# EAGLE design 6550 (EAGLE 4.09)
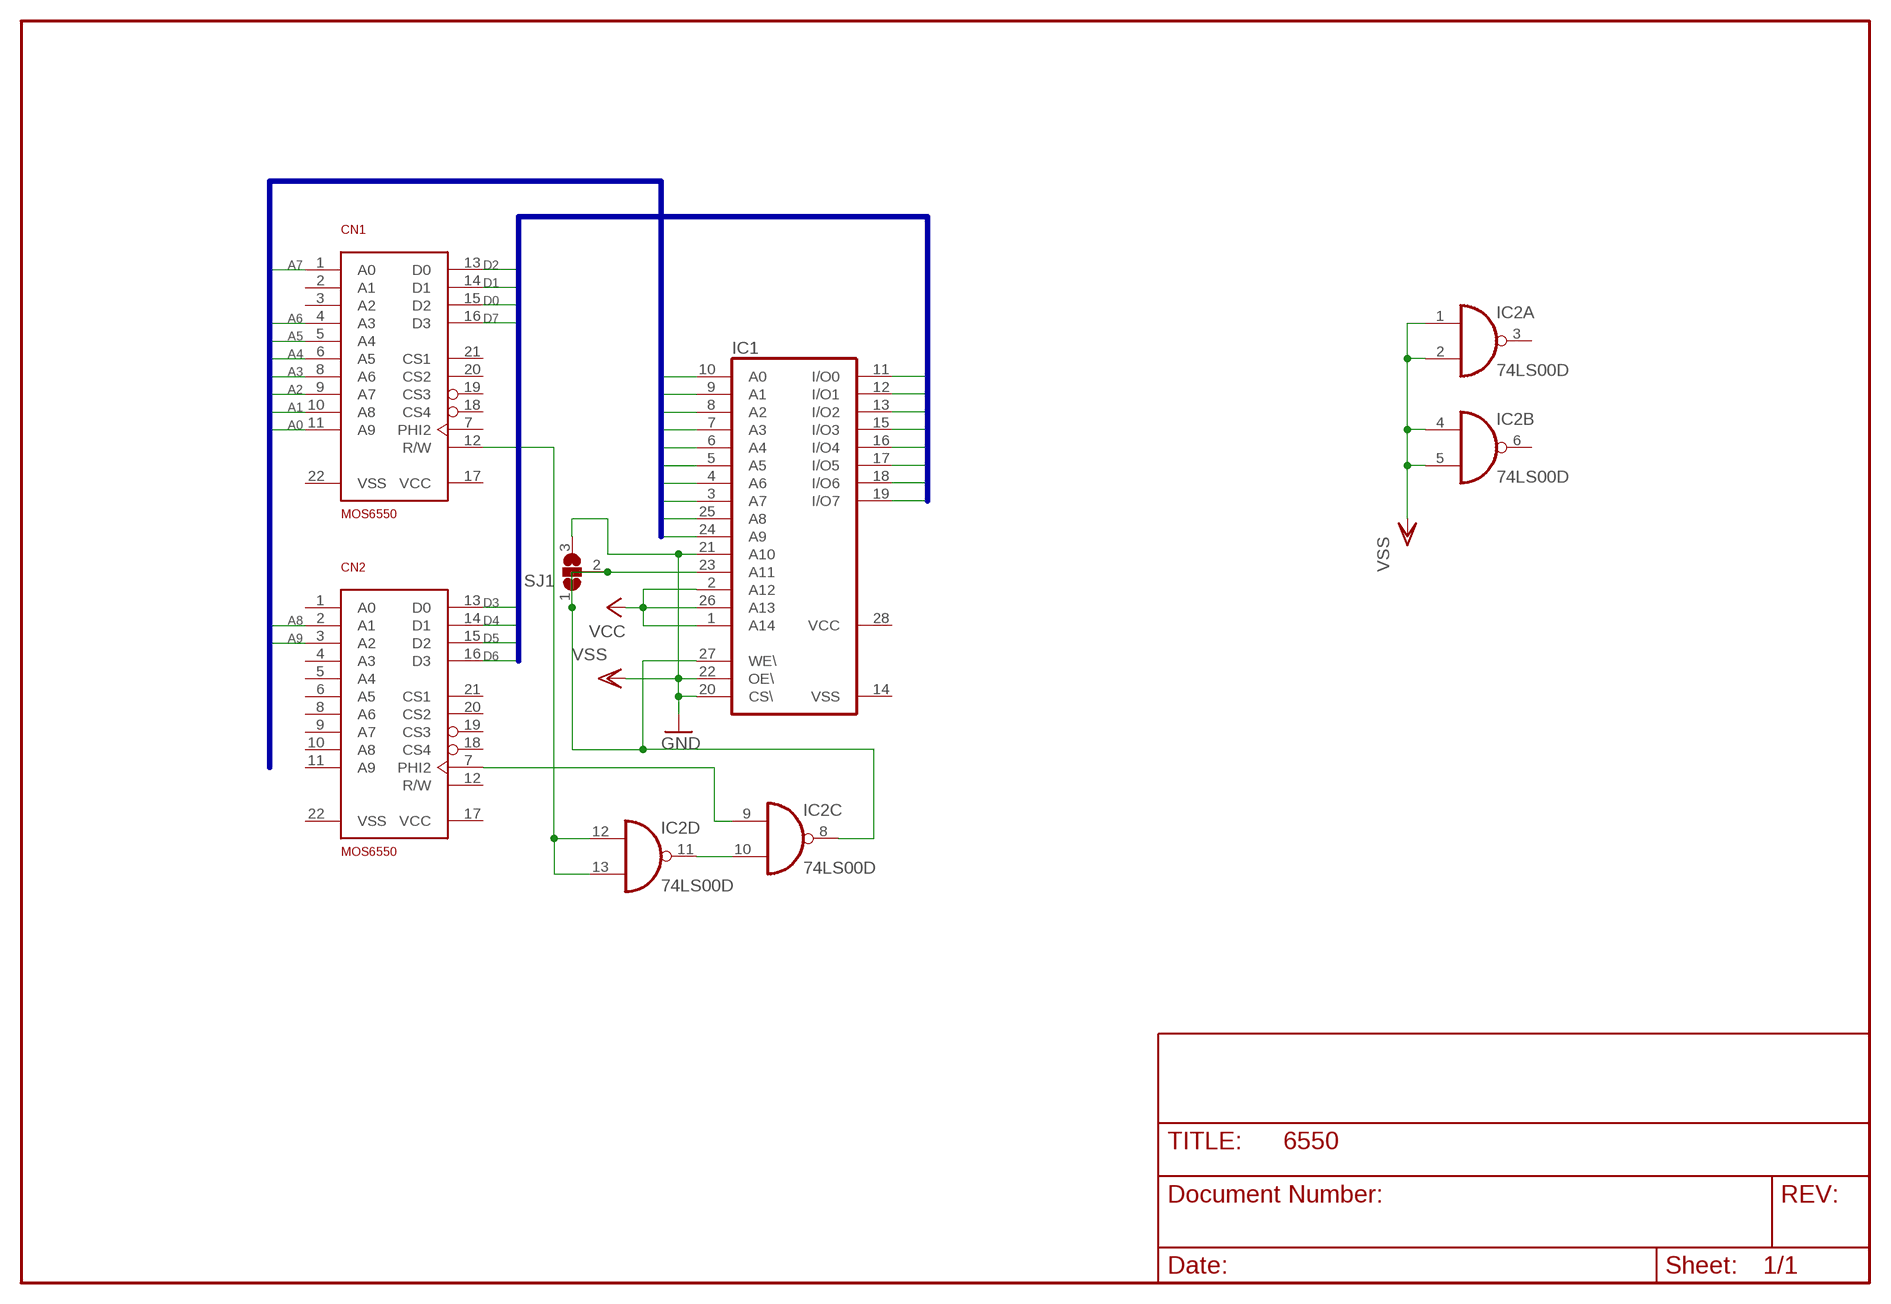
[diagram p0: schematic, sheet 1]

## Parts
CN1  MOS6550  [DIP-22]
CN2  MOS6550  [DIP-22]
IC1  62256P  [DIL28-6]
IC2  74LS00D  [SO14]
SJ1  SJ2W  [SJ_2]

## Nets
A0: CN1.11(A9) IC1.10(A0)
A1: CN1.10(A8) IC1.9(A1)
A2: CN1.9(A7) IC1.8(A2)
A3: CN1.8(A6) IC1.7(A3)
A4: CN1.6(A5) IC1.6(A4)
A5: CN1.5(A4) IC1.5(A5)
A6: CN1.4(A3) IC1.4(A6)
A7: CN1.1(A0) IC1.3(A7)
A8: CN2.2(A1) IC1.25(A8)
A9: CN2.3(A2) IC1.24(A9)
D0: CN1.15(D2) IC1.11(I/O0)
D1: CN1.14(D1) IC1.12(I/O1)
D2: CN1.13(D0) IC1.13(I/O2)
D3: CN2.13(D0) IC1.15(I/O3)
D4: CN2.14(D1) IC1.16(I/O4)
D5: CN2.15(D2) IC1.17(I/O5)
D6: CN2.16(D3) IC1.18(I/O6)
D7: CN1.16(D3) IC1.19(I/O7)
N$1: CN1.12(R/W) IC2.12(D:I0) IC2.13(D:I1)
N$2: IC2.10(C:I1) IC2.11(D:O)
N$3: CN2.7(PHI2) IC2.9(C:I0)
N$4: IC1.23(A11) IC1.27(WE\) IC2.8(C:O) SJ1.1 SJ1.2
VCC: IC1.1(A14) IC1.2(A12) IC1.26(A13)
VSS: IC1.20(CS\) IC1.21(A10) IC1.22(OE\) IC2.1(A:I0) IC2.2(A:I1) IC2.4(B:I0) IC2.5(B:I1) SJ1.3 ; supply symbol labelled GND
Unconnected: CN1.2(A1) CN1.3(A2) CN1.7(PHI2) CN1.18(CS4) CN1.19(CS3) CN1.20(CS2) CN1.21(CS1) CN2.1(A0) CN2.4(A3) CN2.5(A4) CN2.6(A5) CN2.8(A6) CN2.9(A7) CN2.10(A8) CN2.11(A9) CN2.12(R/W) CN2.18(CS4) CN2.19(CS3) CN2.20(CS2) CN2.21(CS1) IC2.3(A:O) IC2.6(B:O)

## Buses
A[0..9]
D[0..7]

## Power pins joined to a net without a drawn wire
VCC: CN1.17(VCC) CN2.17(VCC) IC1.28(VCC) IC2.14(P:VCC)
VSS: CN1.22(VSS) CN2.22(VSS) IC1.14(VSS) IC2.7(P:GND)

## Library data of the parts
CN1 CN2 = 65XXX:MOS6550
IC1 = memory-hitachi:62256P: MEMORY
IC2 = 74xx-eu:74*00: Quad 2-input NAND gate
SJ1 = jumper:SJ2W: SMD solder JUMPER

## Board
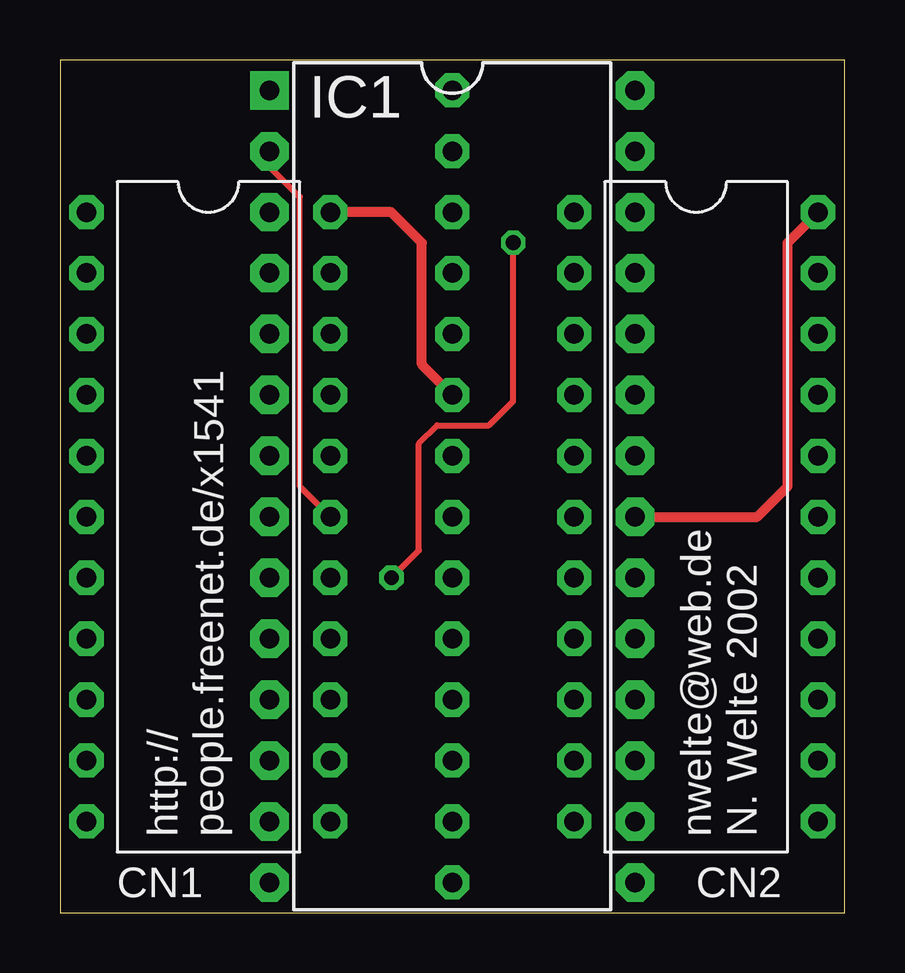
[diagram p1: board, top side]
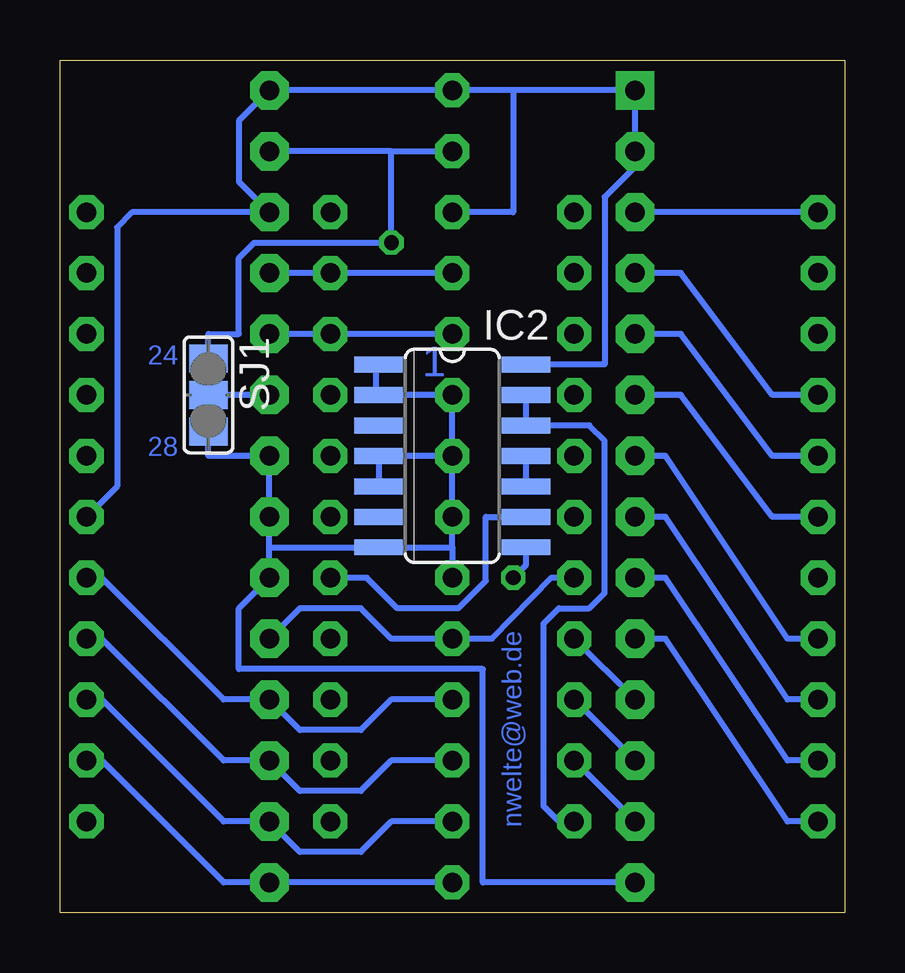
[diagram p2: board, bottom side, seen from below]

Size 32.69 x 35.55 mm. Coordinates in mm from the lower left corner, seen from the top.
Outline: 0,0 32.69,0 32.69,35.55 0,35.55 0,0
Copper layers used: Top, Bottom

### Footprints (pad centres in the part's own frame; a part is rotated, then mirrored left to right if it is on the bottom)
DIP-22 = drill 0.813 pad 1.422 octagon: 1 -5.08,12.7; 2 -5.08,10.16; 3 -5.08,7.62; 4 -5.08,5.08; 5 -5.08,2.54; 6 -5.08,0; 7 -5.08,-2.54; 8 -5.08,-5.08; 9 -5.08,-7.62; 10 -5.08,-10.16; 11 -5.08,-12.7; 12 5.08,-12.7; 13 5.08,-10.16; 14 5.08,-7.62; 15 5.08,-5.08; 16 5.08,-2.54; 17 5.08,0; 18 5.08,2.54; 19 5.08,5.08; 20 5.08,7.62; 21 5.08,10.16; 22 5.08,12.7
DIL28-6 = drill 0.813 pad 1.6 square: 1 -16.51,-7.62 | drill 0.813 pad 1.6 octagon: 2 -13.97,-7.62; 3 -11.43,-7.62; 4 -8.89,-7.62; 5 -6.35,-7.62; 6 -3.81,-7.62; 7 -1.27,-7.62; 8 1.27,-7.62; 9 3.81,-7.62; 10 6.35,-7.62; 11 8.89,-7.62; 12 11.43,-7.62; 13 13.97,-7.62; 14 16.51,-7.62; 15 16.51,7.62; 16 13.97,7.62; 17 11.43,7.62; 18 8.89,7.62; 19 6.35,7.62; 20 3.81,7.62; 21 1.27,7.62; 22 -1.27,7.62; 23 -3.81,7.62; 24 -6.35,7.62; 25 -8.89,7.62; 26 -11.43,7.62; 27 -13.97,7.62; 28 -16.51,7.62
SO14 = smd 0.66 x 2.032: 1 -3.81,-3.073; 2 -2.54,-3.073; 3 -1.27,-3.073; 4 0,-3.073; 5 1.27,-3.073; 6 2.54,-3.073; 7 3.81,-3.073; 8 3.81,3.073; 9 2.54,3.073; 10 1.27,3.073; 11 0,3.073; 12 -1.27,3.073; 13 -2.54,3.073; 14 -3.81,3.073
SJ_2 = smd 1.168 x 1.6: 1 -1.524,0; 2 0,0; 3 1.524,0

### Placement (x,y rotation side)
CN1  6.18,16.51 0 top
CN2  26.5,16.51 0 top
IC1  16.34,17.78 270 top
IC2  16.34,19.05 270 bottom
SJ1  26.5,21.59 270 bottom

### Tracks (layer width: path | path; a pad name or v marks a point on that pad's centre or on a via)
A0
  Bottom 0.254: CN1.11 2.38,3.81 7.46,11.42 IC1.10
A1
  Bottom 0.254: CN1.10 2.38,6.34 7.46,13.96 IC1.9
A2
  Bottom 0.254: CN1.9 2.38,8.88 7.46,16.51 IC1.8
A3
  Bottom 0.254: CN1.8 2.38,11.42 7.46,19.05 IC1.7
A4
  Bottom 0.254: CN1.6 3.01,16.51 6.82,21.59 IC1.6
A5
  Bottom 0.254: CN1.5 3.01,19.05 6.82,24.12 IC1.5
A6
  Bottom 0.254: CN1.4 3.01,21.59 6.82,26.67 IC1.4
A7
  Bottom 0.254: CN1.1 IC1.3
A8  (via drill 0.81 pad 1.42)
  Bottom 0.254: v16.34,26.67 CN2.2 | CN2.2 IC1.25 CN2.2
A9  (via drill 0.81 pad 1.42)
  Bottom 0.254: v16.34,24.12 CN2.3 | CN2.3 IC1.24 CN2.3
D0
  Bottom 0.254: IC1.11 CN1.15
D1
  Bottom 0.254: IC1.12 CN1.14
D2
  Bottom 0.254: IC1.13 CN1.13
D3  (via drill 0.81 pad 1.42)
  Bottom 0.254: CN2.13 30.95,6.34 25.87,1.27 IC1.15 v16.34,1.27
D4  (via drill 0.81 pad 1.42)
  Bottom 0.254: CN2.14 30.95,8.88 25.87,3.81 IC1.16 22.7,2.54 20.16,2.54 18.88,3.81 v16.34,3.81
D5  (via drill 0.81 pad 1.42)
  Bottom 0.254: CN2.15 30.95,11.42 25.87,6.34 IC1.17 22.7,5.08 20.16,5.08 18.88,6.34 v16.34,6.34
D6  (via drill 0.81 pad 1.42)
  Bottom 0.254: CN2.16 30.95,13.96 25.87,8.88 IC1.18 22.7,7.62 20.16,7.62 18.88,8.88 v16.34,8.88
D7  (via drill 0.81 pad 1.42)
  Bottom 0.254: IC1.19 22.7,12.69 20.16,12.69 18.88,11.42 v16.34,11.42 14.69,11.42 12.22,13.96 CN1.16
N$1
  Bottom 0.254: CN1.12 11.9,3.81 12.54,4.44 12.54,12.06 11.9,12.69 10.63,12.69 9.99,13.33 9.99,19.68 10.63,20.32 IC2.12 13.27,21.48 13.17,21.59 IC2.13
N$2
  Bottom 0.254: IC2.10 13.17,17.78 13.27,17.88 IC2.11
N$3
  Bottom 0.254: IC2.9 14.95,16.51 14.95,13.84 16.09,12.69 18.63,12.69 19.9,13.96 CN2.7
N$4  (via drill 0.61, 0.81 pad 1.42)
  Top 0.254: v13.8,13.96 14.95,15.11 14.95,19.55 15.71,20.32 17.87,20.32 18.88,21.33 v18.88,27.94
  Bottom 0.254: 18.88,31.75 v18.88,27.94 24.6,27.94 25.23,27.3 25.23,24.12 26.5,24.12 SJ1.1 SJ1.2 IC1.23 | 18.88,31.75 v16.34,31.75 | 18.88,31.75 IC1.27 | 13.17,15.23 IC2.8 13.27,14.5 v13.8,13.96
VCC  (via drill 0.81 pad 1.42)
  Top 0.254: CN1.17 9.99,17.78 9.99,29.84 8.72,31.11 IC1.2
  Bottom 0.254: 13.8,34.28 IC1.1 IC1.2 8.72,31.11 9.99,29.84 9.99,22.86 IC2.14 | 13.8,34.28 13.8,29.21 v16.34,29.21 | 13.8,34.28 v16.34,34.28 IC1.28 25.23,33.02 25.23,30.48 IC1.26 29.68,29.21 30.32,28.57 30.32,17.78 CN2.17
VSS  (via drill 0.81 pad 1.42)
  Top 0.406: v16.34,21.59 15.07,22.86 15.07,27.94 13.8,29.21 CN1.22 | CN2.22 30.32,27.94 30.32,17.78 29.04,16.51 IC1.21
  Bottom 0.254: IC1.14 15.07,1.27 15.07,10.15 25.23,10.15 25.23,12.69 IC1.20 23.96,15.23 | v16.34,19.05 v16.34,21.59 19.52,21.59 | v16.34,19.05 v16.34,16.51 16.34,15.23 | 23.96,15.23 IC1.21 IC1.22 26.5,19.05 SJ1.3 26.5,20.32 | 16.34,15.23 v16.34,13.96 | IC2.7 19.52,15.23 | IC2.7 16.34,15.23 | 23.96,15.23 IC2.7 | 19.52,21.59 IC2.2 | IC2.1 19.52,22.75 19.52,21.59 | IC2.4 19.52,19.05 | IC2.5 19.52,17.78 19.42,17.88 IC2.4 | v16.34,19.05 IC2.4

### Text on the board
Bottom: 24 | 1 | 28 | nwelte@web.de
tNames: http:// | people.freenet.de/x1541 | nwelte@web.de | N. Welte 2002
